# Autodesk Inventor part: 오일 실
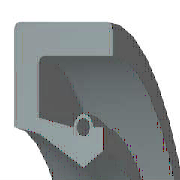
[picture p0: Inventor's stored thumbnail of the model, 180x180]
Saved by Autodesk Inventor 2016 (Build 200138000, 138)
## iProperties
IsCustomPart: 1
Created: 2015-12
Part Number: 오일 실
Material: 고무
Description: 오일-실
Document SubType Name: Modeling
Standard: KS B 2804
Designer: mdu
Standards Organization: KS
Language: ko-KR
Size Designation: S - 15 30 7
Categories: <MemberInstance><Categories><Category DisplayName="샤프트 부품" InternalName="7f7aeb1f-a693-4053-b835-cee3144e0d98" Mnemonic="SHFT"><Category DisplayName="실링" Intern
Density: 0.93 g/cm^3
Appearance: 고무 - 검은색 - 버전 1.1
Mass: 1.64364 g
Surface Area: 26.6454 cm^2
Volume: 1.76736 cm^3
Author: mdu
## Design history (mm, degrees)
revolve "본체" stored, may be unused: angle "d17" = 90 deg
revolve "스프링1" stored, may be unused: angle "d18" = 90 deg
body "Solid1"
sketch "스케치1"
  geometry: L1 (0, 15)-(7, 15); L2 (7, 15)-(7, 13.75); L3 (7, 13.75)-(1.75, 13.75); L4 (0, 15)-(0, 9.6); L5 (0, 9.6)-(1.75, 9.25); L6 (1.75, 9.25)-(4.9, 7.5); L7 (4.9, 7.5)-(0, 7.5); L8 (6.3, 8.375)-(6.3, 9.6); L9 (0, 0)-(9.586, 0) reference; L10 (4.9, 7.5)-(6.3, 8.375); L11 (0, 18)-(0, -3) reference; L12 (-1.917, 0)-(11.503, 0) reference; L13 (4.2, 9.6)-(1.75, 10.09); L14 (1.75, 10.09)-(1.75, 13.75); L15 (6.3, 9.6)-(5.6, 9.6); C1 r 0.455 at (4.9, 9.6); A1 r 0.7 centre (4.9, 9.6) between (5.6, 9.6) and (4.2, 9.6)
  constraints: 26 end point, 5 horizontal alignment, 4 perpendicular, 2 centre point, 2 collinear, 2 horizontal, 2 parallel, 2 point on circle, 2 point on line, 2 vertical alignment, 1 coincident
  dimensions: "d0" = 30 diameter of L1 L9 (= SD2); "d1" = 16.75 diameter of L8.start L9 (= ABDM); "d2" = 1.25 distance of L1.end L2.end (computed from SD); "d3" = 0.91 diameter of C1 (= SPDI); "d4" = 1.4 diameter of A1 (= SPDA); "d5" = 15 diameter of L6.end L9 (= NND); "d6" = 18.5 diameter of L5.end L9 (= TKDM); "d7" = 19.2 diameter of L4.end L9 (= HLDM); "d8" = 4.9 distance from line of C1.centre L4 (= SPDST); "d9" = 6.3 distance between parallel lines of L8 L4 (= SDI); "d10" = 7 distance between parallel lines of L2 L4 (= SWDT); "d12" = 1.75 distance between parallel lines of L14 L4 (= SD)
fillet "모깎기1" dims "d11" = 0.3 (= RR)
other parameters: "SD2" = 30 [user parameter; used in 1 equation term], "SWDT" = 7 [user parameter; used in 1 equation term], "RR" = 0.3 [user parameter; used in 1 equation term], "SD" = 1.75 [user parameter; used in 2 equation terms], "NND" = 15 [user parameter; used in 1 equation term], "SPDA" = 1.4 [user parameter; used in 1 equation term], "SPDI" = 0.91 [user parameter; used in 1 equation term], "TKDM" = 18.5 [user parameter; used in 1 equation term], "HLDM" = 19.2 [user parameter; used in 1 equation term], "ABDM" = 16.75 [user parameter; used in 1 equation term], "SDI" = 6.3 [user parameter; used in 1 equation term], "SPDST" = 4.9 [user parameter; used in 1 equation term], "d13" = 0, "d14" = 0, "d15" = 0, "LAB" = 0.35 [user parameter]
